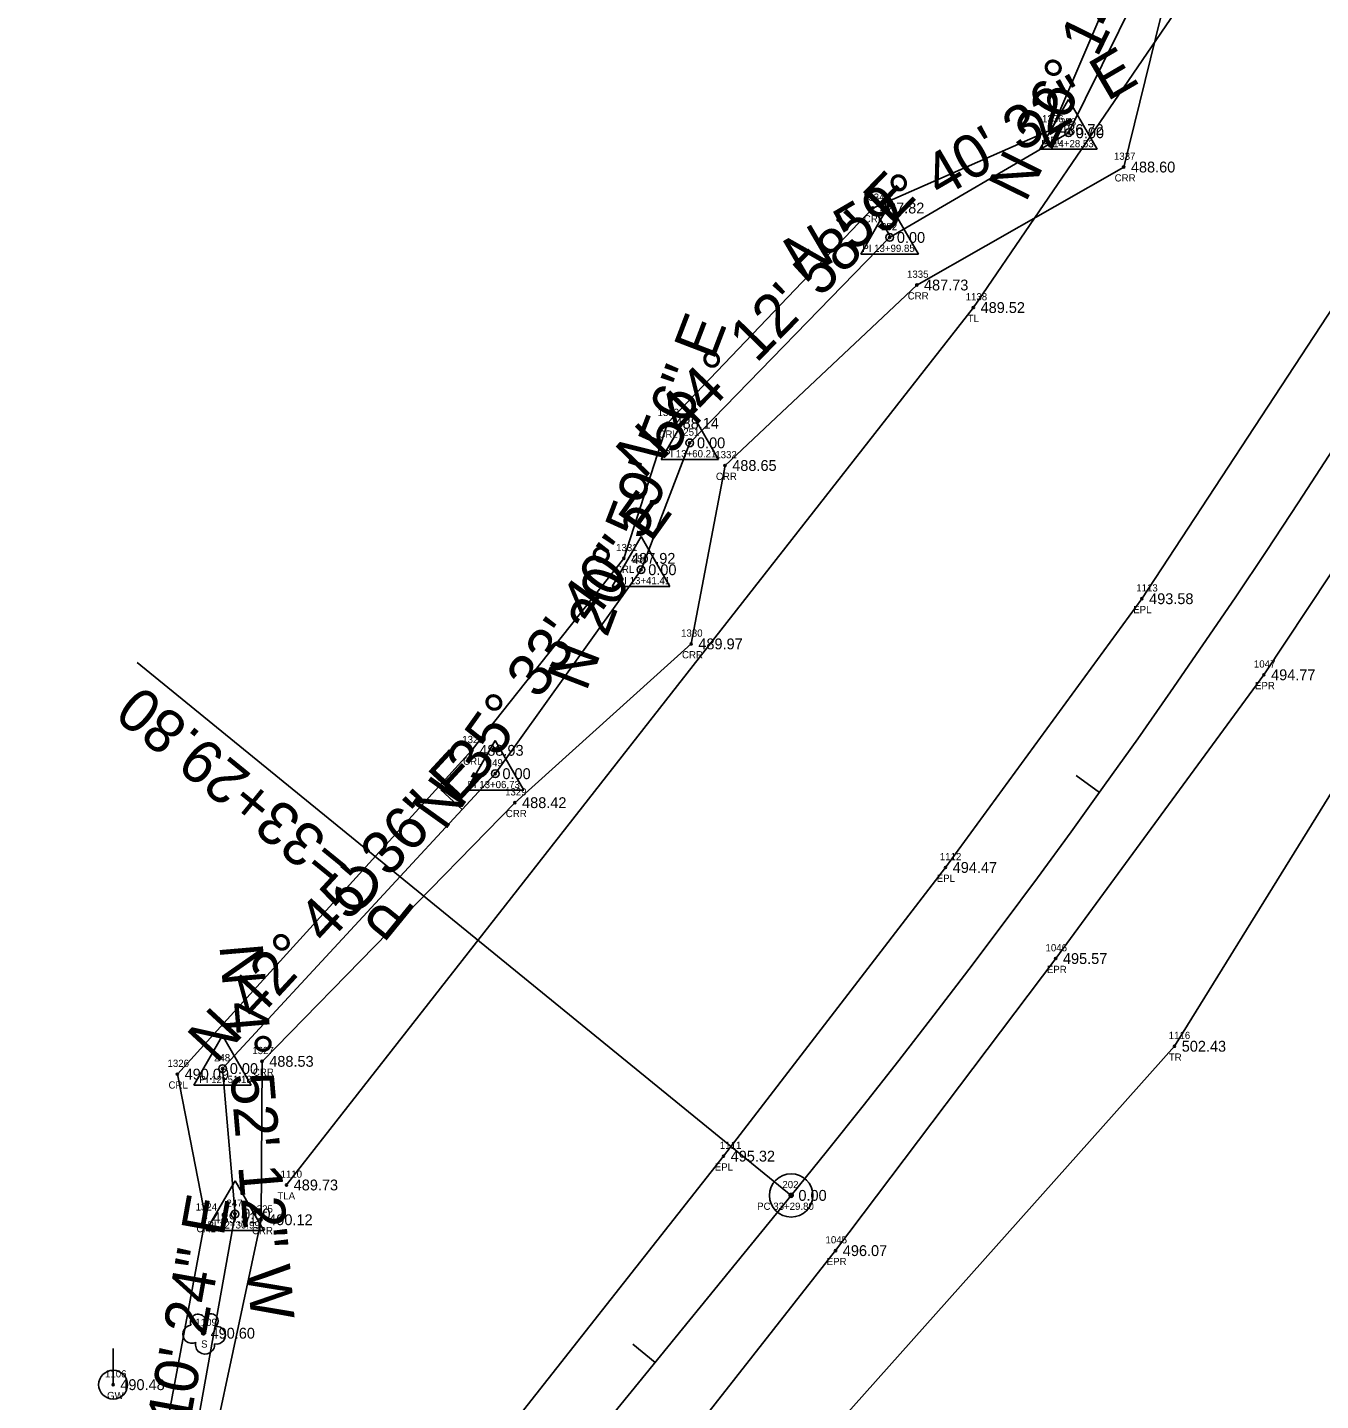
# Model space of a CAD drawing. Extents: x 1649047 to 1650429, y 896228 to 898747.
# Drawn here: x 1649581.4 to 1649760.2, y 897040.7 to 897230.6 of the extents above; entities that cross this region are included whole.
import ezdxf

# ---------------------------------------------------------------- set-up
doc = ezdxf.new("R2010")
doc.units = 0
for name, color, linetype in [('RD_EX_H2O', 7, 'Continuous'), ('RD_EX_H2O_txCode', 7, 'Continuous'), ('RD_EX_Road', 7, 'Continuous'), ('RD_EX_Road_txCode', 7, 'Continuous'), ('RD_EX_TX_H2O_ELEV', 7, 'Continuous'), ('RD_EX_TX_Road_ELEV', 7, 'Continuous'), ('RD_EX_TX_UT_ELEV', 7, 'Continuous'), ('RD_EX_TX_VEG_ELEV', 7, 'Continuous'), ('RD_EX_UT', 7, 'Continuous'), ('RD_EX_UT_txCode', 7, 'Continuous'), ('RD_EX_VEG', 7, 'Continuous'), ('RD_EX_VEG_txCode', 7, 'Continuous'), ('RD_HC_Cl', 7, 'Continuous'), ('RD_HC_Data', 7, 'Continuous'), ('RD_HC_Data_Tic', 7, 'Continuous'), ('RD_HC_Survey_ELEV', 7, 'Continuous'), ('RD_HC_txCode', 7, 'Continuous'), ('RD_SMD_Locator', 7, 'Continuous')]:
    doc.layers.add(name, color=color, linetype=linetype)

msp = doc.modelspace()

# ---------------------------------------------------------------- linework, layer by layer
at = {"layer": 'RD_EX_H2O'}
for points in [[(1649610.78, 897003.58), (1649606.65, 897007.8), (1649603.49, 897018.01), (1649613.66, 897065.71), (1649613.8, 897087.62), (1649648.77, 897123.4), (1649673.15, 897145.36), (1649677.84, 897170.04), (1649704.36, 897195), (1649732.98, 897211.32), (1649741.05, 897244.13), (1649760.18, 897240.39), (1649790.48, 897304.8), (1649814.66, 897340.98), (1649827.92, 897366.62), (1649835.63, 897392.05), (1649839.2, 897413.36), (1649851.88, 897417.91), (1649868.27, 897424.7)], [(1649605.92, 896999), (1649598.21, 896999.47), (1649594.11, 897011.28), (1649598.36, 897025.11), (1649605.96, 897065.98), (1649602.09, 897085.85), (1649642.84, 897130.64), (1649663.84, 897157.19), (1649669.86, 897175.88), (1649698.27, 897205.65), (1649723.06, 897216.5), (1649737.55, 897250.43)]]:
    msp.add_lwpolyline(points, dxfattribs=at)
at = {"layer": 'RD_EX_Road'}
for points in [[(1649459.38, 896805.71), (1649486.55, 896839.62), (1649513.65, 896873.34), (1649538.22, 896902.56), (1649549.43, 896916.62), (1649583.1, 896957.27), (1649614.8, 896995.02), (1649647.06, 897035.69), (1649677.62, 897074.51), (1649708.33, 897114.44), (1649735.5, 897151.61), (1649762.11, 897192.19), (1649788.21, 897235.29), (1649812.17, 897279.73), (1649834.32, 897326.54), (1649852.94, 897371.82), (1649867.51, 897411.96)], [(1649474.75, 896792.65), (1649502.78, 896827.35), (1649565.2, 896903.92), (1649598.28, 896943.71), (1649629.8, 896982.26), (1649667.92, 897029.33), (1649693.13, 897061.44), (1649723.58, 897101.84), (1649752.37, 897141.09), (1649779.72, 897182.3), (1649806.12, 897225.84), (1649830.13, 897270.79), (1649852.39, 897317.43), (1649871.98, 897364.35), (1649886.55, 897406.09)]]:
    msp.add_lwpolyline(points, dxfattribs=at)
at = {"layer": 'RD_EX_UT'}
msp.add_line((1649593.2, 897042.9), (1649593.2, 897047.9), dxfattribs=at)
msp.add_circle((1649593.2, 897042.9), 2, dxfattribs=at)
at = {"layer": 'RD_EX_VEG'}
for points in [[(1649617.18, 897070.52), (1649712.19, 897191.88), (1649745.96, 897241.38), (1649814.66, 897340.98), (1649833.89, 897382.46), (1649865.2, 897454.4), (1649884.45, 897522.02), (1649904.5, 897665.19), (1649923.9, 897762.32), (1649882.75, 898072.18)], [(1649692.17, 896958.45), (1649681.22, 896988.83), (1649682.34, 897025.02), (1649740.01, 897089.71), (1649819.17, 897217.64), (1649850.28, 897262.86), (1649861.15, 897270.14), (1649933.62, 897283.21)]]:
    msp.add_lwpolyline(points, dxfattribs=at)
msp.add_circle((1649605.68, 897050.02), 0.25, dxfattribs=at)
for centre, radius, start, end in [((1649604.96, 897051.57), 1.08, 34.9763, 204.756), ((1649606.72, 897051.72), 0.995, 308.7626, 152.0467), ((1649604.11, 897049.87), 1.26, 96.4518, 294.734), ((1649607.52, 897049.74), 1.22, 256.5667, 98.1046), ((1649605.92, 897048.43), 1.32, 166.8827, 5.7589)]:
    msp.add_arc(centre, radius, start, end, dxfattribs=at)
at = {"layer": 'RD_HC_Cl'}
for p, q in [((1649725.36, 897216.06), (1649740, 897245.76)), ((1649700.61, 897201.58), (1649725.36, 897216.06)), ((1649672.96, 897173.17), (1649700.61, 897201.58)), ((1649666.22, 897155.62), (1649672.96, 897173.17)), ((1649646.05, 897127.41), (1649666.22, 897155.62)), ((1649608.34, 897086.62), (1649646.05, 897127.41)), ((1649610.06, 897066.5), (1649608.34, 897086.62)), ((1649309.97, 896606.4), (1649686.99, 897069.08)), ((1649601.39, 897018.19), (1649610.06, 897066.5))]:
    msp.add_line(p, q, dxfattribs=at)
msp.add_arc((1648799.37, 897792.37), 1145, 320.82481, 10.99954, dxfattribs=at)
at = {"layer": 'RD_HC_Data'}
for p, q in [((1649721.38, 897213.77), (1649725.36, 897220.65)), ((1649725.36, 897220.65), (1649729.33, 897213.77)), ((1649721.38, 897213.77), (1649729.33, 897213.77)), ((1649696.63, 897199.29), (1649700.61, 897206.17)), ((1649700.61, 897206.17), (1649704.58, 897199.29)), ((1649696.63, 897199.29), (1649704.58, 897199.29)), ((1649668.99, 897170.87), (1649672.96, 897177.75)), ((1649672.96, 897177.75), (1649676.93, 897170.87)), ((1649668.99, 897170.87), (1649676.93, 897170.87)), ((1649662.25, 897153.32), (1649666.22, 897160.2)), ((1649666.22, 897160.2), (1649670.19, 897153.32)), ((1649662.25, 897153.32), (1649670.19, 897153.32)), ((1649686.99, 897069.08), (1649596.53, 897142.8)), ((1649642.08, 897125.11), (1649646.05, 897131.99)), ((1649646.05, 897131.99), (1649650.02, 897125.11)), ((1649642.08, 897125.11), (1649650.02, 897125.11)), ((1649604.37, 897084.33), (1649608.34, 897091.21)), ((1649608.34, 897091.21), (1649612.31, 897084.33)), ((1649604.37, 897084.33), (1649612.31, 897084.33)), ((1649606.08, 897064.21), (1649610.06, 897071.09)), ((1649610.06, 897071.09), (1649614.03, 897064.21)), ((1649606.08, 897064.21), (1649614.03, 897064.21))]:
    msp.add_line(p, q, dxfattribs=at)
for centre, radius in [((1649725.36, 897216.06), 0.529), ((1649700.61, 897201.58), 0.529), ((1649672.96, 897173.17), 0.529), ((1649666.22, 897155.62), 0.529), ((1649646.05, 897127.41), 0.529), ((1649608.34, 897086.62), 0.529), ((1649686.99, 897069.08), 3), ((1649686.99, 897069.08), 0.282), ((1649610.06, 897066.5), 0.529)]:
    msp.add_circle(centre, radius, dxfattribs=at)
at = {"layer": 'RD_HC_Data_Tic'}
for p, q in [((1649700.73, 897201.66), (1649698.71, 897205.11)), ((1649729.64, 897124.83), (1649726.39, 897127.16)), ((1649641.48, 897122.47), (1649638.55, 897125.18)), ((1649668.17, 897045.98), (1649665.07, 897048.51))]:
    msp.add_line(p, q, dxfattribs=at)
at = {"layer": 'RD_SMD_Locator'}
for centre in [(1649723.06, 897216.5), (1649725.36, 897216.06), (1649732.98, 897211.32), (1649698.27, 897205.65), (1649700.61, 897201.58), (1649704.36, 897195), (1649712.19, 897191.88), (1649669.86, 897175.88), (1649672.96, 897173.17), (1649677.84, 897170.04), (1649663.84, 897157.19), (1649666.22, 897155.62), (1649735.5, 897151.61), (1649673.15, 897145.36), (1649752.37, 897141.09), (1649642.84, 897130.64), (1649646.05, 897127.41), (1649648.77, 897123.4), (1649708.33, 897114.44), (1649723.58, 897101.84), (1649740.01, 897089.71), (1649613.8, 897087.62), (1649602.09, 897085.85), (1649608.34, 897086.62), (1649677.62, 897074.51), (1649617.18, 897070.52), (1649686.99, 897069.08), (1649605.96, 897065.98), (1649610.06, 897066.5), (1649613.66, 897065.71), (1649693.13, 897061.44), (1649605.68, 897050.02), (1649593.2, 897042.9)]:
    msp.add_circle(centre, 0.15, dxfattribs=at)

# ---------------------------------------------------------------- texts
at = {"layer": 'RD_EX_H2O_txCode'}
for s, p in [('1336', (1649721.69, 897217.5)), ('CRL', (1649721.83, 897214.5)), ('1337', (1649731.63, 897212.32)), ('CRR', (1649731.73, 897209.32)), ('1334', (1649696.92, 897206.65)), ('CRL', (1649697.04, 897203.65)), ('1335', (1649703.01, 897196)), ('CRR', (1649703.11, 897193)), ('1333', (1649668.51, 897176.88)), ('CRL', (1649668.63, 897173.88)), ('1332', (1649676.49, 897171.04)), ('CRR', (1649676.58, 897168.04)), ('1331', (1649662.77, 897158.19)), ('CRL', (1649662.61, 897155.19)), ('1330', (1649671.76, 897146.36)), ('CRR', (1649671.89, 897143.36)), ('1328', (1649641.49, 897131.64)), ('CRL', (1649641.61, 897128.64)), ('1329', (1649647.42, 897124.4)), ('CRR', (1649647.52, 897121.4)), ('1327', (1649612.45, 897088.62)), ('1326', (1649600.72, 897086.85)), ('CRR', (1649612.54, 897085.62)), ('CRL', (1649600.86, 897083.85)), ('1324', (1649604.61, 897066.98)), ('1325', (1649612.32, 897066.71)), ('CRL', (1649604.73, 897063.98)), ('CRR', (1649612.41, 897063.71))]:
    msp.add_text(s, height=1, dxfattribs=at).set_placement(p)
at = {"layer": 'RD_EX_Road_txCode'}
for s, p in [('1113', (1649734.72, 897152.61)), ('EPL', (1649734.3, 897149.61)), ('1047', (1649750.99, 897142.09)), ('EPR', (1649751.14, 897139.09)), ('1112', (1649707.55, 897115.44)), ('EPL', (1649707.12, 897112.44)), ('1046', (1649722.17, 897102.84)), ('EPR', (1649722.35, 897099.84)), ('1111', (1649677.12, 897075.51)), ('EPL', (1649676.42, 897072.51)), ('1045', (1649691.74, 897062.44)), ('EPR', (1649691.9, 897059.44))]:
    msp.add_text(s, height=1, dxfattribs=at).set_placement(p)
at = {"layer": 'RD_EX_TX_H2O_ELEV'}
for s, p in [('486.72', (1649724.06, 897215.75)), ('488.60', (1649733.98, 897210.57)), ('487.82', (1649699.27, 897204.9)), ('487.73', (1649705.36, 897194.25)), ('488.14', (1649670.86, 897175.13)), ('488.65', (1649678.84, 897169.29)), ('487.92', (1649664.84, 897156.44)), ('489.97', (1649674.15, 897144.61)), ('488.93', (1649643.84, 897129.89)), ('488.42', (1649649.77, 897122.65)), ('488.53', (1649614.8, 897086.87)), ('490.09', (1649603.09, 897085.1)), ('489.51', (1649606.96, 897065.23)), ('490.12', (1649614.66, 897064.96))]:
    msp.add_text(s, height=1.5, dxfattribs=at).set_placement(p)
at = {"layer": 'RD_EX_TX_Road_ELEV'}
for s, p in [('493.58', (1649736.5, 897150.86)), ('494.77', (1649753.37, 897140.34)), ('494.47', (1649709.33, 897113.69)), ('495.57', (1649724.58, 897101.09)), ('495.32', (1649678.62, 897073.76)), ('496.07', (1649694.13, 897060.69))]:
    msp.add_text(s, height=1.5, dxfattribs=at).set_placement(p)
at = {"layer": 'RD_EX_TX_UT_ELEV'}
msp.add_text('490.48', height=1.5, dxfattribs=at).set_placement((1649594.2, 897042.15))
at = {"layer": 'RD_EX_TX_VEG_ELEV'}
for s, p in [('489.52', (1649713.19, 897191.13)), ('502.43', (1649741.01, 897088.96)), ('489.73', (1649618.18, 897069.77)), ('490.60', (1649606.68, 897049.27))]:
    msp.add_text(s, height=1.5, dxfattribs=at).set_placement(p)
at = {"layer": 'RD_EX_UT_txCode'}
for s, p in [('1106', (1649592.08, 897043.9)), ('GW', (1649592.36, 897040.9))]:
    msp.add_text(s, height=1, dxfattribs=at).set_placement(p)
at = {"layer": 'RD_EX_VEG_txCode'}
for s, p in [('1138', (1649711.12, 897192.88)), ('TL', (1649711.41, 897189.88)), ('1116', (1649739.21, 897090.71)), ('TR', (1649739.22, 897087.71)), ('1110', (1649616.36, 897071.52)), ('TLA', (1649615.92, 897068.52)), ('1109', (1649604.58, 897051.02)), ('S', (1649605.37, 897048.02))]:
    msp.add_text(s, height=1, dxfattribs=at).set_placement(p)
at = {"layer": 'RD_HC_Data'}
for s, rotation, p in [('N 26%%d 14\' 28" E', 63.759, (1649719.41, 897206.26)), ('N 59%%d 40\' 32" E', 30.3245, (1649688.32, 897195.56)), ('N 44%%d 12\' 58" E', 45.784, (1649666.55, 897168.02)), ('N 20%%d 59\' 56" E', 69.0012, (1649658.63, 897138.63)), ('N 35%%d 33\' 40" E', 54.439, (1649639.05, 897119.33)), ('PC=33+29.80', 140.8248, (1649635.34, 897108.59)), ('N 42%%d 45\' 36" E', 47.2399, (1649607.47, 897087.15)), ('N 4%%d 52\' 12" W', 274.87, (1649607.89, 897103.67)), ('N 10%%d 10\' 24" E', 79.8265, (1649599.8, 897014.98))]:
    msp.add_text(s, height=6, rotation=rotation, dxfattribs=at).set_placement(p)
at = {"layer": 'RD_HC_Survey_ELEV'}
for p in [(1649726.36, 897215.31), (1649701.61, 897200.83), (1649673.96, 897172.42), (1649667.22, 897154.87), (1649647.05, 897126.66), (1649609.34, 897085.87), (1649687.99, 897068.33), (1649611.06, 897065.75)]:
    msp.add_text('0.00', height=1.5, dxfattribs=at).set_placement(p)
at = {"layer": 'RD_HC_txCode'}
for s, p in [('253', (1649724.17, 897217.06)), ('PI 14+28.53', (1649721.58, 897214.06)), ('252', (1649699.42, 897202.58)), ('PI 13+99.85', (1649696.83, 897199.58)), ('251', (1649672.06, 897174.17)), ('PI 13+60.21', (1649669.4, 897171.17)), ('250', (1649665, 897156.62)), ('PI 13+41.41', (1649663.01, 897153.62)), ('249', (1649644.87, 897128.41)), ('PI 13+06.73', (1649642.21, 897125.41)), ('248', (1649607.16, 897087.62)), ('PI 12+51.18', (1649605.13, 897084.62)), ('202', (1649685.77, 897070.08)), ('247', (1649608.87, 897067.5)), ('PC 33+29.80', (1649682.28, 897067.08)), ('PI 12+30.99', (1649606.24, 897064.5))]:
    msp.add_text(s, height=1, dxfattribs=at).set_placement(p)

doc.saveas('drawing.dxf')
